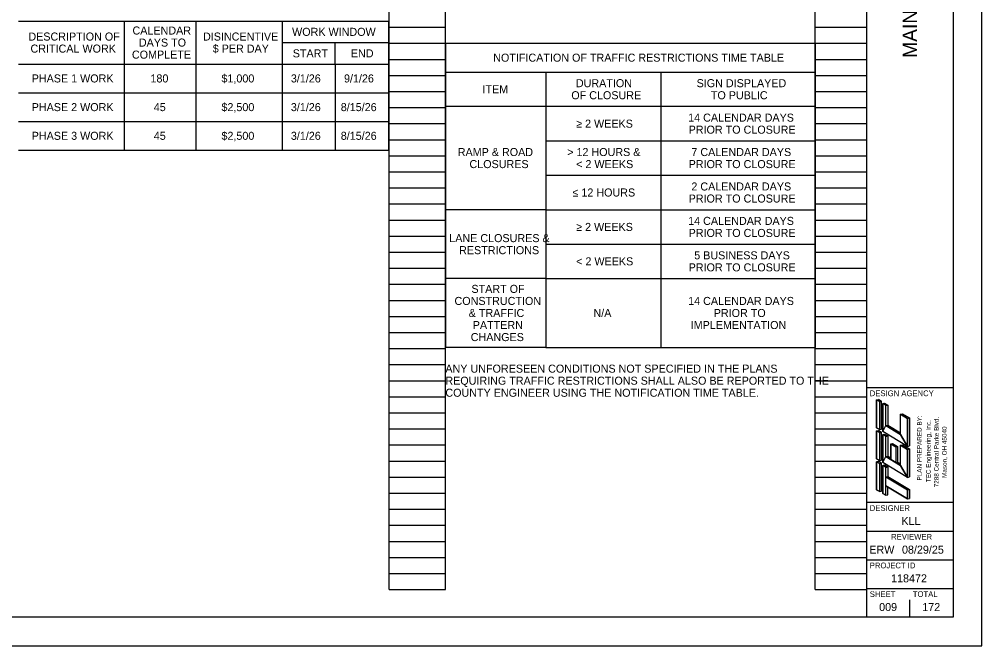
# Model space of a CAD drawing. Extents: x -65.5 to 34, y -24.3 to 23.1.
# Drawn here: x 17.24 to 34, y 0 to 10.92 of the extents above; entities that cross this region are included whole.
import ezdxf

# ---------------------------------------------------------------- set-up
doc = ezdxf.new("R2010")
doc.units = 0
for name, color, linetype in [('Default', 7, 'Continuous'), ('SH_Border', 7, 'Continuous'), ('SH_Cut_Line', 7, 'Continuous'), ('SH_Data', 7, 'Continuous'), ('SH_Text', 7, 'Continuous')]:
    doc.layers.add(name, color=color, linetype=linetype)

msp = doc.modelspace()

# ---------------------------------------------------------------- linework, layer by layer
at = {"layer": 'SH_Border'}
for p, q in [((32, 0.5), (32, 21.5)), ((32, 4.5), (33.5, 4.5)), ((32, 2.5), (33.5, 2.5)), ((32, 2), (33.5, 2)), ((32, 1.5), (33.5, 1.5)), ((32, 1), (33.5, 1))]:
    msp.add_line(p, q, dxfattribs=at)
msp.add_lwpolyline([(1.5, 21.5), (33.5, 21.5), (33.5, 0.5), (1.5, 0.5)], close=True, dxfattribs=at)
at = {"layer": 'SH_Cut_Line'}
msp.add_lwpolyline([(0, 0), (34, 0), (34, 22), (0, 22)], close=True, dxfattribs=at)
at = {"layer": 'SH_Data'}
for p, q in [((23.68, 0.98), (23.68, 21.14)), ((24.66, 0.98), (24.66, 21.14)), ((31.1, 0.98), (31.1, 21.14)), ((32, 0.98), (32, 21.14)), ((23.68, 10.78), (24.66, 10.78)), ((31.1, 10.78), (32, 10.78)), ((23.68, 10.5), (24.66, 10.5)), ((31.1, 10.5), (32, 10.5)), ((23.68, 10.22), (24.66, 10.22)), ((31.1, 10.22), (32, 10.22)), ((23.68, 9.94), (24.66, 9.94)), ((31.1, 9.94), (32, 9.94)), ((23.68, 9.66), (24.66, 9.66)), ((31.1, 9.66), (32, 9.66)), ((23.68, 9.38), (24.66, 9.38)), ((31.1, 9.38), (32, 9.38)), ((23.68, 9.1), (24.66, 9.1)), ((31.1, 9.1), (32, 9.1)), ((23.68, 8.82), (24.66, 8.82)), ((31.1, 8.82), (32, 8.82)), ((23.68, 8.54), (24.66, 8.54)), ((31.1, 8.54), (32, 8.54)), ((23.68, 8.26), (24.66, 8.26)), ((31.1, 8.26), (32, 8.26)), ((23.68, 7.98), (24.66, 7.98)), ((31.1, 7.98), (32, 7.98)), ((23.68, 7.7), (24.66, 7.7)), ((31.1, 7.7), (32, 7.7)), ((23.68, 7.42), (24.66, 7.42)), ((31.1, 7.42), (32, 7.42)), ((23.68, 7.14), (24.66, 7.14)), ((31.1, 7.14), (32, 7.14)), ((23.68, 6.86), (24.66, 6.86)), ((31.1, 6.86), (32, 6.86)), ((23.68, 6.58), (24.66, 6.58)), ((31.1, 6.58), (32, 6.58)), ((23.68, 6.3), (24.66, 6.3)), ((31.1, 6.3), (32, 6.3)), ((23.68, 6.02), (24.66, 6.02)), ((31.1, 6.02), (32, 6.02)), ((23.68, 5.74), (24.66, 5.74)), ((31.1, 5.74), (32, 5.74)), ((23.68, 5.46), (24.66, 5.46)), ((31.1, 5.46), (32, 5.46)), ((23.68, 5.18), (24.66, 5.18)), ((31.1, 5.18), (32, 5.18)), ((23.68, 4.9), (24.66, 4.9)), ((31.1, 4.9), (32, 4.9)), ((23.68, 4.62), (24.66, 4.62)), ((31.1, 4.62), (32, 4.62)), ((23.68, 4.34), (24.66, 4.34)), ((31.1, 4.34), (32, 4.34)), ((23.68, 4.06), (24.66, 4.06)), ((31.1, 4.06), (32, 4.06)), ((23.68, 3.78), (24.66, 3.78)), ((31.1, 3.78), (32, 3.78)), ((23.68, 3.5), (24.66, 3.5)), ((31.1, 3.5), (32, 3.5)), ((32.75, 3.5), (32.75, 3.5)), ((23.68, 3.22), (24.66, 3.22)), ((31.1, 3.22), (32, 3.22)), ((23.68, 2.94), (24.66, 2.94)), ((31.1, 2.94), (32, 2.94)), ((23.68, 2.66), (24.66, 2.66)), ((31.1, 2.66), (32, 2.66)), ((23.68, 2.38), (24.66, 2.38)), ((31.1, 2.38), (32, 2.38)), ((23.68, 2.1), (24.66, 2.1)), ((31.1, 2.1), (32, 2.1)), ((23.68, 1.82), (24.66, 1.82)), ((31.1, 1.82), (32, 1.82)), ((23.68, 1.54), (24.66, 1.54)), ((31.1, 1.54), (32, 1.54)), ((23.68, 1.26), (24.66, 1.26)), ((31.1, 1.26), (32, 1.26)), ((23.68, 0.98), (24.66, 0.98)), ((31.1, 0.98), (32, 0.98)), ((32.375, 0.675), (32.375, 0.675)), ((32.75, 0.5), (32.75, 0.8))]:
    msp.add_line(p, q, dxfattribs=at)
at = {"layer": 'SH_Text'}
for p, q in [((19.067, 10.888), (19.067, 10.138)), ((20.317, 10.888), (20.317, 10.138)), ((21.817, 10.888), (21.817, 10.138)), ((23.667, 10.888), (23.667, 10.138)), ((21.817, 10.513), (23.667, 10.513)), ((22.742, 10.138), (22.742, 10.513)), ((24.66, 10.5), (31.1, 10.5)), ((24.66, 10.5), (24.66, 10)), ((31.1, 10.5), (31.1, 10)), ((19.067, 10.138), (19.067, 9.638)), ((20.317, 10.138), (20.317, 9.638)), ((21.817, 10.138), (21.817, 9.638)), ((22.742, 10.138), (22.742, 9.638)), ((23.667, 10.138), (23.667, 9.638)), ((24.66, 10), (31.1, 10)), ((24.66, 10), (24.66, 9.4)), ((26.41, 10), (26.41, 9.4)), ((28.41, 10), (28.41, 9.4)), ((31.1, 10), (31.1, 9.4)), ((19.067, 9.638), (19.067, 9.138)), ((20.317, 9.638), (20.317, 9.138)), ((21.817, 9.638), (21.817, 9.138)), ((22.742, 9.638), (22.742, 9.138)), ((23.667, 9.638), (23.667, 9.138)), ((24.66, 9.4), (24.66, 7.6)), ((26.41, 9.4), (24.66, 9.4)), ((26.41, 9.4), (26.41, 7.6)), ((28.41, 9.4), (26.41, 9.4)), ((28.41, 9.4), (28.41, 8.8)), ((31.1, 9.4), (28.41, 9.4)), ((31.1, 9.4), (31.1, 8.8)), ((19.067, 9.138), (19.067, 8.638)), ((20.317, 9.138), (20.317, 8.638)), ((21.817, 9.138), (21.817, 8.638)), ((22.742, 9.138), (22.742, 8.638)), ((23.667, 9.138), (23.667, 8.638)), ((26.41, 8.8), (28.41, 8.8)), ((28.41, 8.8), (31.1, 8.8)), ((28.41, 8.8), (28.41, 8.2)), ((31.1, 8.8), (31.1, 8.2)), ((26.41, 8.2), (28.41, 8.2)), ((28.41, 8.2), (31.1, 8.2)), ((28.41, 8.2), (28.41, 7.6)), ((31.1, 8.2), (31.1, 7.6)), ((26.41, 7.6), (24.66, 7.6)), ((24.66, 7.6), (24.66, 6.4)), ((26.41, 7.6), (28.41, 7.6)), ((26.41, 7.6), (26.41, 6.4)), ((28.41, 7.6), (31.1, 7.6)), ((28.41, 7.6), (28.41, 7)), ((31.1, 7.6), (31.1, 7)), ((26.41, 7), (28.41, 7)), ((28.41, 7), (28.41, 6.4)), ((28.41, 7), (31.1, 7)), ((31.1, 7), (31.1, 6.4)), ((26.41, 6.4), (24.66, 6.4)), ((24.66, 6.4), (24.66, 5.2)), ((26.41, 6.4), (28.41, 6.4)), ((26.41, 6.4), (26.41, 5.2)), ((28.41, 6.4), (31.1, 6.4)), ((28.41, 6.4), (28.41, 5.2)), ((31.1, 6.4), (31.1, 5.2)), ((26.41, 5.2), (24.66, 5.2)), ((26.41, 5.2), (28.41, 5.2)), ((28.41, 5.2), (31.1, 5.2)), ((32.169, 4.285), (32.201, 4.294)), ((32.169, 3.799), (32.169, 4.285)), ((32.223, 4.253), (32.169, 4.285)), ((32.255, 4.261), (32.201, 4.294)), ((32.223, 4.253), (32.255, 4.261)), ((32.223, 3.767), (32.223, 4.253)), ((32.255, 3.775), (32.255, 4.261)), ((32.277, 4.221), (32.309, 4.229)), ((32.331, 4.188), (32.277, 4.221)), ((32.277, 3.735), (32.277, 4.221)), ((32.309, 4.229), (32.363, 4.196)), ((32.331, 4.188), (32.363, 4.196)), ((32.363, 4.196), (32.363, 3.845)), ((32.331, 3.837), (32.331, 4.188)), ((32.587, 4.034), (32.62, 4.042)), ((32.587, 3.683), (32.587, 4.034)), ((32.709, 3.961), (32.587, 4.034)), ((32.62, 4.042), (32.741, 3.97)), ((32.709, 3.961), (32.741, 3.97)), ((32.709, 3.475), (32.709, 3.961)), ((32.741, 3.97), (32.741, 3.484)), ((32.223, 3.767), (32.169, 3.799)), ((32.169, 3.745), (32.201, 3.754)), ((32.169, 3.259), (32.169, 3.745)), ((32.223, 3.713), (32.169, 3.745)), ((32.255, 3.722), (32.201, 3.754)), ((32.223, 3.767), (32.255, 3.775)), ((32.223, 3.713), (32.255, 3.722)), ((32.223, 3.227), (32.223, 3.713)), ((32.255, 3.236), (32.255, 3.722)), ((32.709, 3.475), (32.277, 3.735)), ((32.277, 3.681), (32.309, 3.689)), ((32.309, 3.689), (32.363, 3.656)), ((32.331, 3.837), (32.363, 3.845)), ((32.587, 3.683), (32.331, 3.837)), ((32.363, 3.845), (32.587, 3.711)), ((32.277, 3.195), (32.277, 3.681)), ((32.331, 3.648), (32.277, 3.681)), ((32.331, 3.648), (32.363, 3.656)), ((32.331, 3.297), (32.331, 3.648)), ((32.363, 3.656), (32.363, 3.305)), ((32.415, 3.519), (32.448, 3.527)), ((32.448, 3.527), (32.535, 3.474)), ((32.415, 3.519), (32.415, 3.247)), ((32.415, 3.519), (32.503, 3.466)), ((32.503, 3.466), (32.535, 3.474)), ((32.503, 3.466), (32.503, 3.194)), ((32.535, 3.474), (32.535, 3.202)), ((32.587, 3.494), (32.62, 3.502)), ((32.587, 3.143), (32.587, 3.494)), ((32.709, 3.421), (32.587, 3.494)), ((32.62, 3.502), (32.741, 3.43)), ((32.709, 3.475), (32.741, 3.484)), ((32.709, 3.421), (32.741, 3.43)), ((32.709, 2.935), (32.709, 3.421)), ((32.741, 3.43), (32.741, 2.944)), ((32.223, 3.227), (32.169, 3.259)), ((32.169, 3.205), (32.201, 3.215)), ((32.169, 2.719), (32.169, 3.205)), ((32.223, 3.173), (32.169, 3.205)), ((32.255, 3.181), (32.201, 3.215)), ((32.223, 3.227), (32.255, 3.236)), ((32.709, 2.935), (32.277, 3.195)), ((32.331, 3.297), (32.363, 3.305)), ((32.415, 3.247), (32.331, 3.297)), ((32.363, 3.305), (32.415, 3.274)), ((32.503, 3.194), (32.535, 3.202)), ((32.587, 3.143), (32.503, 3.194)), ((32.535, 3.202), (32.587, 3.171)), ((32.222, 3.173), (32.255, 3.181)), ((32.223, 2.687), (32.223, 3.173)), ((32.255, 2.695), (32.255, 3.181)), ((32.277, 3.141), (32.309, 3.151)), ((32.331, 3.108), (32.277, 3.141)), ((32.277, 2.655), (32.277, 3.141)), ((32.309, 3.151), (32.363, 3.116)), ((32.331, 3.108), (32.363, 3.116)), ((32.331, 2.944), (32.331, 3.108)), ((32.363, 3.116), (32.363, 2.952)), ((32.331, 2.944), (32.363, 2.952)), ((32.331, 2.944), (32.709, 2.717)), ((32.363, 2.952), (32.741, 2.725)), ((32.709, 2.935), (32.741, 2.944)), ((32.223, 2.687), (32.169, 2.719)), ((32.223, 2.687), (32.255, 2.695)), ((32.331, 2.787), (32.709, 2.56)), ((32.331, 2.622), (32.331, 2.787)), ((32.363, 2.63), (32.363, 2.767)), ((32.709, 2.717), (32.741, 2.725)), ((32.709, 2.56), (32.709, 2.717)), ((32.741, 2.725), (32.741, 2.568)), ((32.331, 2.622), (32.277, 2.655)), ((32.331, 2.622), (32.363, 2.63)), ((32.709, 2.56), (32.741, 2.568))]:
    msp.add_line(p, q, dxfattribs=at)
for points in [[(17.227, 10.888), (19.067, 10.888), (20.317, 10.888), (21.817, 10.888), (23.667, 10.888)], [(17.227, 10.138), (19.067, 10.138), (20.317, 10.138), (21.817, 10.138), (22.742, 10.138), (23.667, 10.138)], [(17.227, 9.638), (19.067, 9.638), (20.317, 9.638), (21.817, 9.638), (22.742, 9.638), (23.667, 9.638)], [(17.227, 9.138), (19.067, 9.138), (20.317, 9.138), (21.817, 9.138), (22.742, 9.138), (23.667, 9.138)], [(17.227, 8.638), (19.067, 8.638), (20.317, 8.638), (21.817, 8.638), (22.742, 8.638), (23.667, 8.638)]]:
    msp.add_lwpolyline(points, dxfattribs=at)
for points in [[(32.169, 3.799), (32.223, 3.767), (32.223, 4.253), (32.169, 4.285)], [(32.277, 3.735), (32.331, 3.837), (32.331, 4.188), (32.277, 4.221)], [(32.709, 3.475), (32.587, 3.683), (32.587, 4.034), (32.709, 3.961)], [(32.169, 3.259), (32.223, 3.227), (32.223, 3.713), (32.169, 3.745)], [(32.277, 3.735), (32.331, 3.837), (32.587, 3.683), (32.709, 3.475)], [(32.277, 3.195), (32.331, 3.297), (32.331, 3.648), (32.277, 3.681)], [(32.415, 3.247), (32.415, 3.519), (32.503, 3.466), (32.503, 3.194)], [(32.709, 2.935), (32.587, 3.143), (32.587, 3.494), (32.709, 3.421)], [(32.169, 2.719), (32.223, 2.687), (32.223, 3.173), (32.169, 3.205)], [(32.277, 3.195), (32.331, 3.297), (32.587, 3.143), (32.709, 2.935)], [(32.277, 2.655), (32.331, 2.622), (32.331, 3.108), (32.277, 3.141)], [(32.331, 2.787), (32.331, 2.944), (32.709, 2.717), (32.709, 2.56)]]:
    msp.add_lwpolyline(points, close=True, dxfattribs=at)

# ---------------------------------------------------------------- texts
at = {"layer": 'Default'}
for s, p in [('PLAN PREPARED BY:', (32.954, 2.88)), ('TEC Engineering, Inc.', (33.11, 2.851)), ('7288 Central Parke Blvd.', (33.25, 2.762)), ('Mason, OH 45040', (33.39, 2.925))]:
    msp.add_text(s, height=0.08, rotation=90, dxfattribs=at).set_placement(p)
at = {"layer": 'SH_Data'}
msp.add_text('MAINTENANCE OF TRAFFIC NOTES', height=0.25, rotation=90, dxfattribs=at).set_placement((32.875, 10.247))
for s, height, p in [('DESIGN AGENCY', 0.1, (32.05, 4.35)), ('DESIGNER', 0.1, (32.05, 2.35)), ('KLL', 0.14, (32.601, 2.105)), ('REVIEWER', 0.1, (32.422, 1.85)), ('ERW', 0.14, (32.042, 1.605)), ('08/29/25', 0.14, (32.611, 1.605)), ('PROJECT ID', 0.1, (32.05, 1.35)), ('118472', 0.14, (32.421, 1.105)), ('SHEET', 0.1, (32.05, 0.85)), ('TOTAL', 0.1, (32.8, 0.85)), ('009', 0.14, (32.213, 0.605)), ('172', 0.14, (32.964, 0.605))]:
    msp.add_text(s, height=height, dxfattribs=at).set_placement(p)
at = {"layer": 'SH_Text'}
for s, p in [('CALENDAR ', (19.212, 10.653)), ('WORK WINDOW', (21.991, 10.63)), ('DESCRIPTION OF ', (17.399, 10.548)), ('DAYS TO ', (19.323, 10.443)), ('DISINCENTIVE ', (20.44, 10.548)), ('CRITICAL WORK', (17.436, 10.338)), ('$ PER DAY', (20.609, 10.338)), ('START', (22.002, 10.255)), ('END', (23.014, 10.255)), ('COMPLETE', (19.202, 10.233)), ('NOTIFICATION OF TRAFFIC RESTRICTIONS TIME TABLE', (25.493, 10.18)), ('PHASE 1 WORK', (17.457, 9.818)), ('180', (19.525, 9.818)), ('$1,000', (20.761, 9.818)), ('3/1/26', (21.97, 9.818)), ('9/1/26', (22.895, 9.818)), ('ITEM', (25.306, 9.63)), ('DURATION', (26.932, 9.735)), ('SIGN DISPLAYED', (29.035, 9.735)), ('OF CLOSURE', (26.853, 9.525)), ('TO PUBLIC', (29.283, 9.525)), ('PHASE 2 WORK', (17.457, 9.318)), ('45', (19.583, 9.318)), ('$2,500', (20.761, 9.318)), ('3/1/26', (21.97, 9.318)), ('8/15/26', (22.839, 9.318)), ('14 CALENDAR DAYS', (28.888, 9.135)), ('≥ 2 WEEKS', (26.938, 9.03)), ('PRIOR TO CLOSURE', (28.896, 8.925)), ('PHASE 3 WORK', (17.457, 8.818)), ('45', (19.583, 8.818)), ('$2,500', (20.761, 8.818)), ('3/1/26', (21.97, 8.818)), ('8/15/26', (22.839, 8.818)), ('RAMP & ROAD', (24.876, 8.535)), ('> 12 HOURS &', (26.782, 8.535)), ('7 CALENDAR DAYS', (28.944, 8.535)), ('CLOSURES', (25.08, 8.325)), ('< 2 WEEKS', (26.938, 8.325)), ('PRIOR TO CLOSURE', (28.896, 8.325)), ('2 CALENDAR DAYS', (28.944, 7.935)), ('≤ 12 HOURS', (26.874, 7.83)), ('PRIOR TO CLOSURE', (28.896, 7.725)), ('14 CALENDAR DAYS', (28.888, 7.335)), ('≥ 2 WEEKS', (26.938, 7.23)), ('PRIOR TO CLOSURE', (28.896, 7.125)), ('LANE CLOSURES &', (24.728, 7.035)), ('RESTRICTIONS', (24.899, 6.825)), ('5 BUSINESS DAYS', (28.994, 6.735)), ('< 2 WEEKS', (26.938, 6.63)), ('PRIOR TO CLOSURE', (28.896, 6.525)), ('START OF ', (25.114, 6.15)), ('CONSTRUCTION ', (24.819, 5.94)), ('14 CALENDAR DAYS', (28.888, 5.94)), ('& TRAFFIC ', (25.067, 5.73)), ('N/A', (27.239, 5.73)), ('PRIOR TO', (29.333, 5.73)), ('PATTERN ', (25.137, 5.52)), ('IMPLEMENTATION', (28.932, 5.52)), ('CHANGES', (25.102, 5.31)), ('ANY UNFORESEEN CONDITIONS NOT SPECIFIED IN THE PLANS ', (24.66, 4.76)), ('REQUIRING TRAFFIC RESTRICTIONS SHALL ALSO BE REPORTED TO THE ', (24.66, 4.55)), ('COUNTY ENGINEER USING THE NOTIFICATION TIME TABLE.', (24.66, 4.34))]:
    msp.add_text(s, height=0.14, dxfattribs=at).set_placement(p)

doc.saveas('drawing.dxf')
